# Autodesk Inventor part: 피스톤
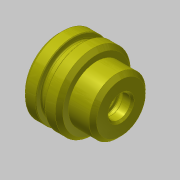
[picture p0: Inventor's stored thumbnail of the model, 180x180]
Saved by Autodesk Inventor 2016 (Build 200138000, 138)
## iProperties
Created: 2020-02
Part Number: 피스톤
Material: 강철, 탄소
Document SubType Name: Modeling
Designer: mduedu
Density: 1 g/cm^3
Appearance: 노란색
Author: mduedu
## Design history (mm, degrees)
sketch "스케치1"
  geometry: L1 (0, 0)-(20, 0); L2 (20, 0)-(20, 20); L3 (20, 20)-(0, 20); L4 (0, 20)-(0, 0); L5 (20, 0)-(33, 0); L6 (33, 0)-(33, 15); L7 (33, 15)-(20, 15); L8 (20, 15)-(20, 0)
  constraints: 16 end point, 4 parallel, 2 horizontal, 2 perpendicular
  dimensions: "d0" = 33 distance between parallel lines of L6 L4; "d2" = 20 distance of L2.end L3.end; "d3" = 40 diameter of L3 L1; "d4" = 30 diameter of L7 L5
revolve "회전1" sketch "스케치1" stored, may be unused: angle "d5" = 90 deg
sketch "스케치2"
  geometry: L1 (0, -20)-(0, 20) reference; L2 (0, 20)-(20, 20) reference; L3 (20, 20)-(20, 15) reference; L4 (20, 15)-(33, 15) reference; L5 (33, 15)-(33, -15) reference; L6 (33, -15)-(20, -15) reference; L7 (20, -15)-(20, -20) reference; L8 (20, -20)-(0, -20) reference; L9 (0, 0)-(20, 0); L10 (20, 0)-(20, 11); L11 (20, 11)-(0, 11); L12 (0, 11)-(0, 0); L13 (33, 0)-(20, 0); L14 (20, 0)-(20, 6); L15 (20, 6)-(33, 6); L16 (33, 6)-(33, 0)
  constraints: 16 end point, 4 parallel, 2 horizontal, 2 perpendicular, 1 midpoint, 1 point on line
  dimensions: "d6" = 22 diameter of L11 L9; "d8" = 12 diameter of L15 L13; "d9" = 20 distance of L10.end L11.end
revolve "회전2" sketch "스케치2" stored, may be unused: angle "d10" = 90 deg
chamfer "모따기1" distance "d11" = 2; stored, may be unused: second distance "d12" = 2, angle "d13" = 45 deg
sketch "스케치3"
  geometry: L1 (20, -11)-(20, -6) reference; L2 (20, -6)-(33, -6) reference; L3 (33, -6)-(33, -13) reference; L4 (33, -13)-(31, -15) reference; L5 (31, -15)-(20, -15) reference; L6 (20, -15)-(20, -18) reference; L7 (20, -18)-(18, -20) reference; L8 (18, -20)-(2, -20) reference; L9 (2, -20)-(0, -18) reference; L10 (0, -18)-(0, -11) reference; L11 (0, -11)-(20, -11) reference; L12 (20, 6)-(20, 11) reference; L13 (20, 11)-(0, 11) reference; L14 (0, 11)-(0, 18) reference; L15 (0, 18)-(2, 20) reference; L16 (2, 20)-(18, 20) reference; L17 (18, 20)-(20, 18) reference; L18 (20, 18)-(20, 15) reference; L19 (20, 15)-(31, 15) reference; L20 (31, 15)-(33, 13) reference; L21 (33, 13)-(33, 6) reference; L22 (33, 6)-(20, 6) reference; L23 (7.65, 20)-(12.35, 20); L24 (12.35, 20)-(12.35, 17); L25 (12.35, 17)-(7.65, 17); L26 (7.65, 17)-(7.65, 20); L27 (24.4, 6)-(27.6, 6); L28 (27.6, 6)-(27.6, 8); L29 (27.6, 8)-(24.4, 8); L30 (24.4, 8)-(24.4, 6); L31 (10, 17)-(10, 20); L32 (26, 6)-(26, 8); L33 (-6.6, 0)-(39.6, 0) reference; 1 further point
  constraints: 20 end point, 4 midpoint, 4 parallel, 2 horizontal, 2 perpendicular, 2 point on line
  dimensions: "d14" = 10 distance between parallel lines of L31 L14; "d15" = 7 distance between parallel lines of L32 L21; "d16" = 4.7 distance between parallel lines of L24 L26; "d17" = 34 diameter of L25 L33; "d18" = 16 diameter of L29 L33; "d19" = 3.2 distance of L28.end L29.end
revolve "회전3" sketch "스케치3" stored, may be unused: angle "d20" = 90 deg
fillet "모깎기1" dims "d21" = 0.8
fillet "모깎기2" dims "d22" = 0.4
chamfer "모따기2" distance "d23" = 0.3; stored, may be unused: second distance "d24" = 2, angle "d25" = 45 deg
chamfer "모따기3" distance "d26" = 0.3; stored, may be unused: second distance "d27" = 2, angle "d28" = 45 deg
chamfer "모따기4" distance "d29" = 1; stored, may be unused: second distance "d30" = 2, angle "d31" = 45 deg
node "솔리드1"
node "절단 모서리 투영1"
node "절단 모서리 투영2"
